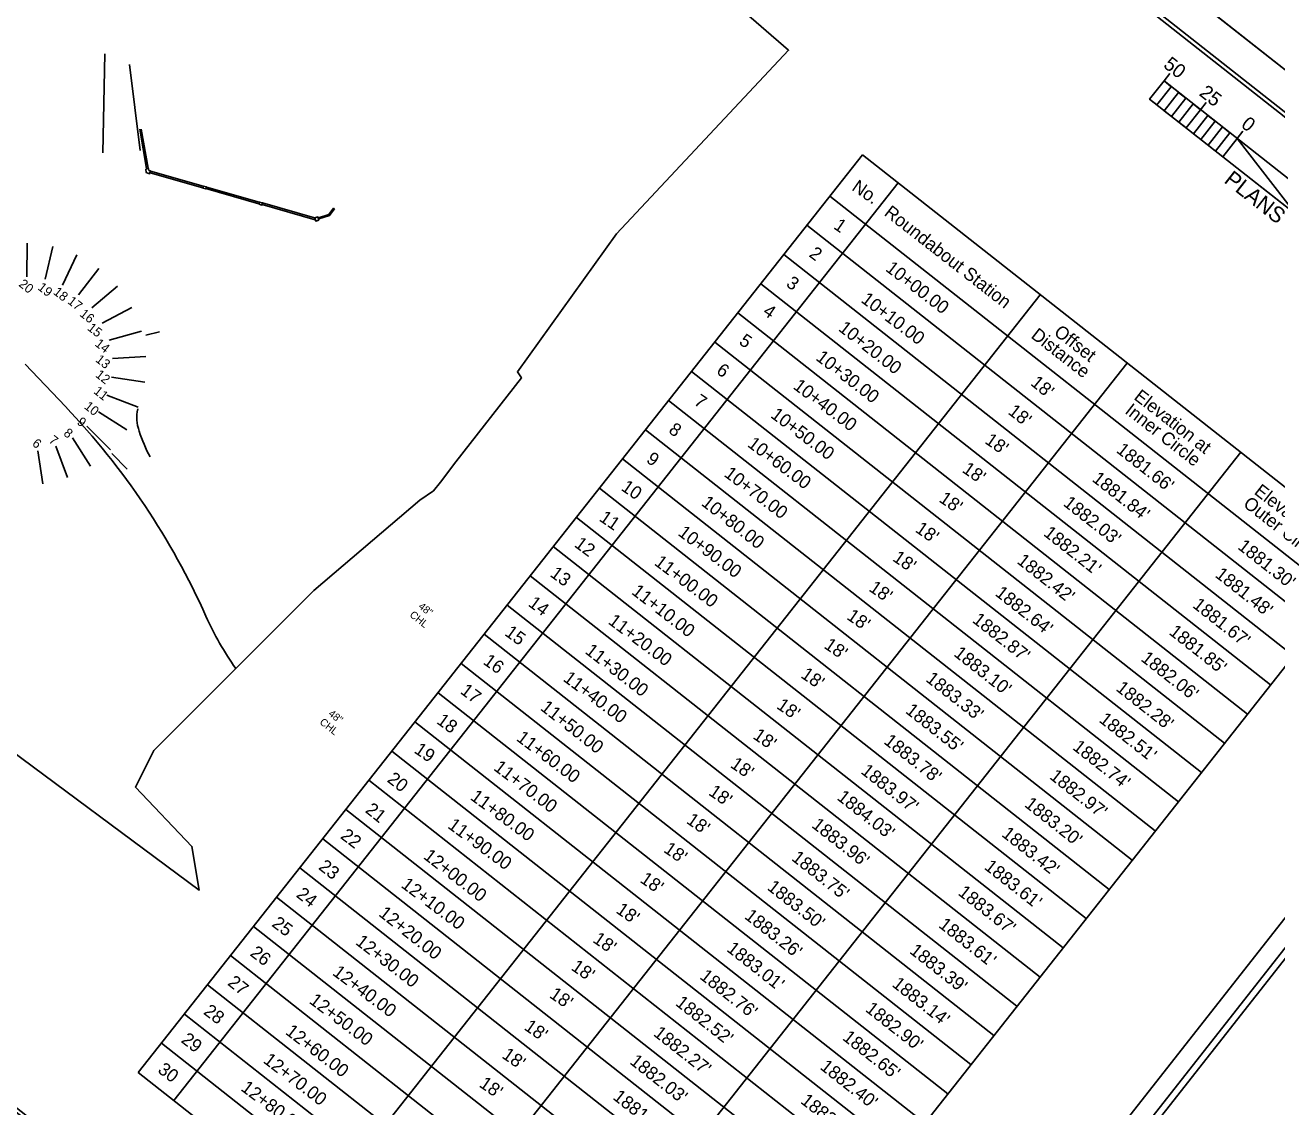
# Model space of a CAD drawing. Extents: x 556999 to 560450, y 504801 to 507732.
# Drawn here: x 557693 to 558366, y 506524 to 507105 of the extents above; entities that cross this region are included whole.
import ezdxf

# ---------------------------------------------------------------- set-up
doc = ezdxf.new("R2010")
doc.units = 0
for name, color, linetype in [('Default', 7, 'Continuous'), ('Exist Roads EOP', 7, 'Continuous'), ('Prop Dimension', 7, 'Continuous'), ('Prop Dimension Text', 7, 'Continuous'), ('Prop Horizontal Alignment', 7, 'Continuous'), ('Prop Horizontal Alignment Station Label', 7, 'Continuous'), ('Sheet Border Standard 30in CELL', 7, 'Continuous'), ('Sheet Clip Boundary CELL', 7, 'Continuous'), ('Sheet Cutting Line CELL', 7, 'Continuous'), ('Sheet Data Field CELL', 7, 'Continuous'), ('Sheet Plot Border Inside CELL', 7, 'Continuous'), ('Sheet Plot Border Outside CELL', 7, 'Continuous'), ('Sheet Title CELL', 7, 'Continuous')]:
    doc.layers.add(name, color=color, linetype=linetype)

msp = doc.modelspace()

# ---------------------------------------------------------------- linework, layer by layer
at = {"layer": 'Default'}
for p, q in [((557754.15, 507049.33), (557757.8, 507028.18)), ((557755, 507049.36), (557758.71, 507028.36)), ((557759.84, 507025.86), (557788.08, 507017.85)), ((557760.05, 507026.79), (557788.2, 507018.72)), ((557789.79, 507017.42), (557818.21, 507009.26)), ((557790.07, 507018.29), (557818.46, 507010.18)), ((557820.24, 507009.72), (557848.2, 507001.71)), ((557819.98, 507008.83), (557848.46, 507000.62))]:
    msp.add_line(p, q, dxfattribs=at)
for points in [[(557757.42, 507027.9), (557757.7, 507026.01), (557759.48, 507025.43), (557759.94, 507027.06), (557759.12, 507027.18), (557758.98, 507028.19), (557757.42, 507027.9)], [(557788.18, 507017.65), (557789.72, 507017.27), (557790.07, 507018.37), (557788.45, 507018.82), (557788.18, 507017.65)], [(557818.35, 507009), (557819.89, 507008.62), (557820.24, 507009.72), (557818.62, 507010.17), (557818.35, 507009)], [(557850.26, 507001.8), (557855.79, 507003.59), (557858.43, 507007.01)], [(557850.48, 507001.12), (557856.23, 507002.99), (557858.97, 507006.54)], [(557848.33, 507001.81), (557849.99, 507002.22), (557850.45, 507000.51), (557848.8, 507000.01), (557848.33, 507001.81)]]:
    msp.add_lwpolyline(points, dxfattribs=at)
at = {"layer": 'Exist Roads EOP'}
for p, q in [((557734.41, 507036.75), (557735.42, 507089.77)), ((557754.38, 507037.83), (557748.65, 507084.09)), ((557858.43, 507007.01), (557858.97, 507006.54))]:
    msp.add_line(p, q, dxfattribs=at)
at = {"layer": 'Prop Dimension'}
for p, q in [((557693.4, 506970.07), (557693.71, 506988.07)), ((557703.3, 506968.84), (557707.41, 506986.37)), ((557712.73, 506965.55), (557720.44, 506981.81)), ((557721.24, 506960.34), (557732.21, 506974.6)), ((557728.46, 506953.44), (557742.2, 506965.07)), ((557734.06, 506945.18), (557749.95, 506953.65)), ((557737.79, 506935.93), (557755.11, 506940.85)), ((557764.81, 506940.51), (557757.55, 506938.76)), ((557739.49, 506926.09), (557757.45, 506927.24)), ((557739.07, 506916.12), (557756.87, 506913.45)), ((557736.55, 506906.46), (557753.38, 506900.09)), ((557732.05, 506897.55), (557747.16, 506887.77)), ((557725.77, 506889.79), (557738.47, 506877.05)), ((557717.99, 506883.54), (557727.72, 506868.39)), ((557699.4, 506876.58), (557702.01, 506858.77)), ((557709.07, 506879.07), (557715.38, 506862.21)), ((557747.47, 506866.64), (557739.15, 506875.19))]:
    msp.add_line(p, q, dxfattribs=at)
for centre, radius, start, end in [((557772.56, 506894.5), 20, 166.78733, 201.44134), ((557815.07, 506905), 63.67, 196.24977, 209.87175)]:
    msp.add_arc(centre, radius, start, end, dxfattribs=at)
at = {"layer": 'Prop Horizontal Alignment'}
msp.add_line((557692.58, 506923.08), (557714.24, 506900.34), dxfattribs=at)
for centre, radius, start, end in [((557424.61, 506624.45), 400, 24.07862, 43.60768), ((557940.45, 506854.97), 165, 204.07862, 215.30769)]:
    msp.add_arc(centre, radius, start, end, dxfattribs=at)
at = {"layer": 'Prop Horizontal Alignment Station Label'}
for p, q in [((558142.86, 507035.66), (557753.4, 506542.58)), ((558142.86, 507035.66), (558416.94, 506820.13)), ((558161.95, 507020.59), (557772.52, 506527.55)), ((558125.3, 507013.43), (558399.37, 506797.89)), ((558112.9, 506997.73), (558386.98, 506782.2)), ((558100.51, 506982.04), (558374.58, 506766.5)), ((558088.11, 506966.34), (558362.18, 506750.81)), ((558238.26, 506960.32), (557848.96, 506467.44)), ((558075.71, 506950.65), (558349.79, 506735.11)), ((558063.32, 506934.95), (558337.39, 506719.42)), ((558284.85, 506923.51), (557895.63, 506430.73)), ((558050.92, 506919.26), (558324.99, 506703.72)), ((558038.52, 506903.56), (558312.6, 506688.03)), ((558026.13, 506887.87), (558300.2, 506672.33)), ((558346.16, 506875.79), (557956.7, 506382.71)), ((558013.73, 506872.17), (558287.81, 506656.64)), ((558001.33, 506856.48), (558275.41, 506640.95)), ((557988.94, 506840.78), (558263.01, 506625.25)), ((557976.54, 506825.09), (558250.62, 506609.56)), ((558416.82, 506819.98), (558027.36, 506326.9)), ((557964.15, 506809.39), (558238.22, 506593.86)), ((557951.75, 506793.7), (558225.82, 506578.17)), ((557939.35, 506778.01), (558213.43, 506562.47)), ((557926.96, 506762.31), (558201.03, 506546.78)), ((557914.56, 506746.62), (558188.63, 506531.08)), ((557902.16, 506730.92), (558176.24, 506515.39)), ((557889.77, 506715.23), (558163.84, 506499.69)), ((557877.37, 506699.53), (558151.44, 506484)), ((557864.97, 506683.84), (558139.05, 506468.3)), ((557852.58, 506668.14), (558126.65, 506452.61)), ((557840.18, 506652.45), (558114.25, 506436.91)), ((557827.78, 506636.75), (558101.86, 506421.22)), ((557815.39, 506621.06), (558089.46, 506405.52)), ((557802.99, 506605.36), (558077.06, 506389.83)), ((557790.59, 506589.67), (558064.67, 506374.13)), ((557778.2, 506573.97), (558052.27, 506358.44)), ((557765.8, 506558.28), (558039.87, 506342.74)), ((557753.4, 506542.58), (558027.48, 506327.05))]:
    msp.add_line(p, q, dxfattribs=at)
at = {"layer": 'Sheet Border Standard 30in CELL'}
msp.add_lwpolyline([(558579, 506891.48), (557635.74, 507633.27), (557116.49, 506972.99), (558059.75, 506231.2)], close=True, dxfattribs=at)
at = {"layer": 'Sheet Clip Boundary CELL'}
msp.add_lwpolyline([(557670.21, 507466.23), (558103.06, 507091.75), (558010.57, 506993.11), (557957.23, 506919.09), (557959.37, 506915.73), (557924.17, 506870.66), (557915.94, 506859.67), (557912.12, 506855.15), (557904.86, 506850.09), (557847.72, 506801.46), (557761.69, 506715.56), (557751.89, 506695.94), (557782.23, 506664.04), (557786.18, 506640.54), (557672.55, 506724.62), (557610.32, 506776.93), (557401.38, 506939.59), (557410.24, 506997.06), (557374.28, 507190.56)], close=True, dxfattribs=at)
at = {"layer": 'Sheet Cutting Line CELL'}
msp.add_line((558602.06, 506898.8), (557543.09, 507731.58), dxfattribs=at)
at = {"layer": 'Sheet Data Field CELL'}
for p, q in [((558304.9, 507075.3), (558307.98, 507079.22)), ((558324.54, 507059.83), (558327.64, 507063.76))]:
    msp.add_line(p, q, dxfattribs=at)
at = {"layer": 'Sheet Plot Border Inside CELL'}
msp.add_lwpolyline([(558588.12, 506886.9), (557540.16, 507711.03), (557018.38, 507047.54), (558066.35, 506223.41)], close=True, dxfattribs=at)
at = {"layer": 'Sheet Plot Border Outside CELL'}
msp.add_lwpolyline([(558602.06, 506898.8), (557543.09, 507731.58), (556999.11, 507039.85), (558058.08, 506207.07)], close=True, dxfattribs=at)
at = {"layer": 'Sheet Title CELL'}
for p, q in [((558304.88, 507075.29), (558307.97, 507079.21)), ((558307.97, 507079.21), (558307.97, 507079.21)), ((558304.88, 507075.29), (558297.16, 507065.47)), ((558304.88, 507075.29), (558304.88, 507075.29)), ((558422.79, 506982.57), (558304.88, 507075.29)), ((558297.16, 507065.47), (558415.06, 506972.73)), ((558324.53, 507059.83), (558327.63, 507063.77)), ((558332.4, 507053.66), (558324.67, 507043.83)), ((558344.18, 507044.38), (558347.27, 507048.31))]:
    msp.add_line(p, q, dxfattribs=at)
for points in [[(558304.88, 507075.29), (558308.81, 507072.2), (558301.09, 507062.38), (558297.16, 507065.47)], [(558312.74, 507069.11), (558316.67, 507066.01), (558308.94, 507056.19), (558305.02, 507059.27)], [(558320.6, 507062.92), (558324.53, 507059.83), (558316.81, 507050.01), (558312.88, 507053.1)], [(558328.46, 507056.74), (558332.4, 507053.66), (558324.67, 507043.83), (558320.74, 507046.92)], [(558336.33, 507050.57), (558340.26, 507047.48), (558332.52, 507037.64), (558328.6, 507040.74)], [(558344.18, 507044.38), (558375.76, 507003.65), (558336.45, 507034.55)]]:
    msp.add_lwpolyline(points, close=True, dxfattribs=at)

# ---------------------------------------------------------------- texts
at = {"layer": 'Default'}
for s, p in [('48" ', (557903.69, 506792.34)), ('CHL', (557898.94, 506787.81)), ('48" ', (557855.29, 506734.7)), ('CHL', (557850.55, 506730.16))]:
    msp.add_text(s, height=4, rotation=321.66667, dxfattribs=at).set_placement(p)
at = {"layer": 'Prop Dimension Text'}
for s, p in [('20', (557688.75, 506965.39)), ('19', (557698.94, 506963.6)), ('18', (557707.32, 506961.13)), ('17', (557715.01, 506956.17)), ('16', (557721.51, 506949.38)), ('15', (557725.65, 506941.84)), ('14', (557729.72, 506933.34)), ('13', (557730.02, 506924.87)), ('12', (557729.96, 506916.68)), ('11', (557728.99, 506907.86)), ('10', (557723.94, 506899.67)), ('8', (557712.83, 506885.28)), ('9', (557720.06, 506891.28)), ('6', (557695.96, 506879.73)), ('7', (557704.87, 506881.46))]:
    msp.add_text(s, height=5, rotation=321.70536, dxfattribs=at).set_placement(p)
at = {"layer": 'Prop Horizontal Alignment Station Label'}
for s, rotation, p in [('No.', 325.49634, (558136.56, 507016.94)), ('Roundabout Station', 322.10271, (558153.96, 507003.48)), ('1', 325.49634, (558126.79, 506996.29)), ('2', 323.26857, (558113.57, 506981.29)), ('10+00.00', 322.41499, (558154.71, 506973.62)), ('3', 324.86169, (558101.24, 506965.33)), ('10+10.00', 322.88423, (558141.5, 506956.81)), ('4', 325.17959, (558088.73, 506950.18)), ('10+20.00', 321.89906, (558129.39, 506941.48)), ('Distance', 322.10271, (558232.9, 506937.63)), ('Offset ', 322.10271, (558245.22, 506939.29)), ('5', 325.49634, (558075.91, 506934.25)), ('10+30.00', 322.30457, (558117.22, 506925.74)), ('6', 325.49634, (558063.74, 506918.44)), ("18'", 320.52347, (558232.71, 506912.26)), ('10+40.00', 322.98705, (558105.03, 506910.32)), ('Elevation at', 322.10271, (558288.24, 506904.61)), ('7', 325.49634, (558051.68, 506901.8)), ('Inner Circle', 322.10271, (558283.41, 506897.13)), ('10+50.00', 323.00521, (558092.92, 506894.85)), ("18'", 322.06054, (558220.56, 506896.76)), ('8', 325.49634, (558038.04, 506886.57)), ('10+60.00', 322.86368, (558080.45, 506879.23)), ("18'", 325.49634, (558208.1, 506880.94)), ('9', 325.49634, (558026.06, 506870.78)), ("1881.66'", 321.77253, (558278.8, 506876.11)), ("18'", 325.49634, (558195.89, 506865.42)), ('10+70.00', 322.81783, (558067.9, 506863.23)), ("1881.84'", 321.77253, (558265.75, 506860.63)), ('10', 325.49634, (558012.5, 506855.75)), ('Elevation at', 322.10271, (558352.89, 506853.77)), ('10+80.00', 321.73199, (558055.66, 506847.69)), ("18'", 325.49634, (558183.42, 506849.56)), ("1882.03'", 321.77396, (558250.25, 506847.51)), ('Outer Circle', 322.10271, (558347, 506847.11)), ('11', 325.49634, (558000.74, 506839.31)), ('10+90.00', 322.77478, (558043.09, 506831.57)), ("18'", 325.49634, (558170.68, 506833.36)), ("1882.21'", 321.77396, (558239.65, 506831.41)), ('12', 323.30719, (557987.36, 506825.44)), ("1881.30'", 321.77253, (558344.05, 506824.26)), ("18'", 325.49634, (558158.48, 506817.84)), ('11+00.00', 322.90597, (558030.37, 506815.64)), ("1882.42'", 321.77396, (558225.36, 506816.52)), ('13', 323.79697, (557974.31, 506809.47)), ("1881.48'", 321.77396, (558331.9, 506809.15)), ('11+10.00', 322.20673, (558018.15, 506800.01)), ("18'", 325.49634, (558145.74, 506801.64)), ("1882.64'", 321.77396, (558213.65, 506799.2)), ('14', 323.49315, (557962.57, 506793.57)), ("1881.67'", 321.77396, (558319.77, 506792.84)), ('11+20.00', 323.10335, (558005.57, 506784.02)), ("18'", 325.49634, (558133.8, 506786.46)), ("1882.87'", 321.77396, (558201.4, 506784.8)), ('15', 323.89182, (557949.96, 506777.78)), ("1881.85'", 321.77396, (558307.12, 506778.35)), ("18'", 325.49634, (558121.59, 506770.94)), ('11+30.00', 322.19611, (557993.18, 506768.1)), ("1883.10'", 321.77396, (558191.38, 506766.78)), ("1882.06'", 321.77396, (558292, 506764.11)), ('16', 324.59434, (557938.33, 506762.38)), ('11+40.00', 323.16705, (557981.38, 506753.28)), ("18'", 325.49634, (558109.12, 506755.08)), ("1883.33'", 321.77396, (558176.36, 506753.1)), ('17', 322.9039, (557926.05, 506746.63)), ("1882.28'", 321.77396, (558278.59, 506748.13)), ('11+50.00', 321.8634, (557969.15, 506737.69)), ("18'", 325.49634, (558096.12, 506738.54)), ('18', 324.11788, (557913.32, 506730.46)), ("1883.55'", 321.77396, (558165.43, 506736.1)), ("1882.51'", 321.77396, (558269.51, 506731.24)), ('11+60.00', 322.99216, (557956.23, 506721.27)), ("18'", 325.49634, (558083.38, 506722.35)), ("1883.78'", 321.77396, (558153.78, 506719.67)), ("1882.74'", 321.77396, (558255.28, 506716.53)), ('19', 325.49634, (557901.25, 506714.7)), ('11+70.00', 322.78122, (557944.01, 506705.41)), ("18'", 325.49634, (558071.22, 506706.89)), ("1883.97'", 321.77396, (558141.43, 506703.62)), ('20', 322.39763, (557886.76, 506699.11)), ("1882.97'", 321.77396, (558242.89, 506700.78)), ('11+80.00', 323.69357, (557931.43, 506689.58)), ("18'", 325.49634, (558059.55, 506692.04)), ("1884.03'", 321.77396, (558128.6, 506689.54)), ('21', 321.20945, (557874.98, 506682.75)), ("1883.20'", 321.77396, (558229.41, 506685.78)), ("18'", 325.49634, (558047.61, 506676.86)), ('22', 322.80323, (557861.64, 506668.74)), ('11+90.00', 323.58598, (557919.28, 506674.29)), ("1883.96'", 321.77396, (558115.01, 506674.63)), ("1883.42'", 321.77396, (558217.15, 506669.83)), ('12+00.00', 322.21113, (557906.23, 506657.87)), ("18'", 325.49634, (558035.4, 506661.33)), ("1883.75'", 321.77396, (558104.17, 506656.94)), ('23', 322.08324, (557849.85, 506652.15)), ("1883.61'", 321.77396, (558207.79, 506652.23)), ('12+10.00', 323.02254, (557894.22, 506642.44)), ("18'", 325.49634, (558022.66, 506645.14)), ('24', 322.12013, (557837.85, 506637.26)), ("1883.50'", 321.77396, (558091.08, 506641.19)), ("1883.67'", 321.77396, (558193.67, 506638.37)), ("18'", 325.49634, (558009.74, 506628.71)), ('25', 322.98147, (557824.73, 506621.51)), ('12+20.00', 321.60441, (557882.18, 506627.1)), ("1883.26'", 321.77396, (558078.88, 506625.68)), ("1883.61'", 321.77396, (558183.23, 506620.98)), ('12+30.00', 322.25703, (557869.75, 506611.79)), ("18'", 325.49634, (557997.31, 506612.9)), ('26', 322.47636, (557813.02, 506605.75)), ("1883.01'", 321.77396, (558069.28, 506608.13)), ("1883.39'", 321.77396, (558167.63, 506607.04)), ('12+40.00', 323.25692, (557857.36, 506595.32)), ("18'", 325.49634, (557985.63, 506598.05)), ('27', 321.78557, (557800.98, 506589.92)), ("1882.76'", 321.77396, (558054.83, 506593.32)), ("1883.14'", 321.77396, (558158.21, 506589.17)), ("18'", 325.49634, (557973.96, 506583.2)), ('28', 322.9043, (557787.99, 506574.34)), ('12+50.00', 322.85397, (557844.83, 506580.18)), ("1882.52'", 321.77396, (558041.77, 506579.03)), ("1882.90'", 321.77396, (558143.89, 506575.78)), ('12+60.00', 322.29297, (557832.06, 506563.57)), ("18'", 325.49634, (557960.38, 506565.93)), ("1882.27'", 321.77396, (558029.92, 506562.71)), ('29', 322.12068, (557775.99, 506559.17)), ("1882.65'", 321.77396, (558131.58, 506560.49)), ('12+70.00', 322.55523, (557820.15, 506548.19)), ("18'", 325.49634, (557948.43, 506550.75)), ('30', 322.98575, (557763.39, 506542.99)), ("1882.03'", 321.77396, (558017.2, 506547.61)), ("1882.40'", 321.77396, (558119.49, 506544.76)), ("18'", 325.49634, (557936.23, 506535.23)), ('12+80.00', 322.95133, (557808.09, 506533.27)), ("1881.78'", 321.77396, (558008.12, 506528.57)), ("1882.16'", 321.77396, (558109.03, 506526.46))]:
    msp.add_text(s, height=7, rotation=rotation, dxfattribs=at).set_placement(p)
at = {"layer": 'Sheet Title CELL'}
for s, height, p in [('50', 7.5, (558304.06, 507083.03)), ('25', 7.5, (558323.33, 507067.88)), ('0', 7.5, (558345.82, 507050.91)), ('PLANS', 8.5, (558336.64, 507021.04))]:
    msp.add_text(s, height=height, rotation=321.81814, dxfattribs=at).set_placement(p)

doc.saveas('drawing.dxf')
